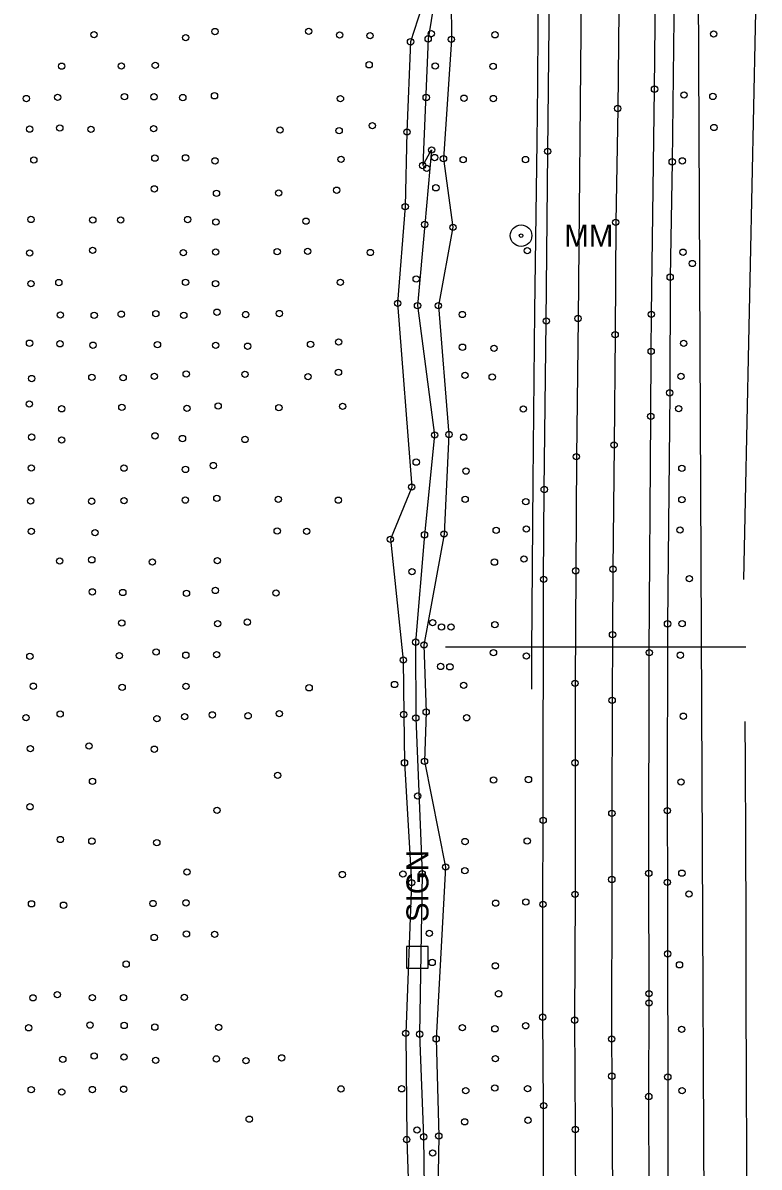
# Model space of a CAD drawing. Extents: x 20503438 to 20508873, y 7964251 to 7984667.
# Drawn here: x 20506380.3 to 20506614, y 7965237.1 to 7965600.1 of the extents above; entities that cross this region are included whole.
import ezdxf

# ---------------------------------------------------------------- set-up
doc = ezdxf.new("R2010")
doc.units = 0
for name, color, linetype in [('PhoSignTrussOverhead', 7, 'Continuous'), ('SurBreakLine', 7, 'Continuous'), ('SurDrainageArrowDown', 7, 'Continuous'), ('SurEdgeRoadPaved', 7, 'Continuous'), ('SurEdgeShoulderPaved', 7, 'Continuous'), ('SurGuardRailCable', 7, 'Continuous'), ('SurPointsNonDTM', 7, 'Continuous'), ('SurRoadPoints', 7, 'Continuous'), ('SurSurveyPoints', 7, 'Continuous')]:
    doc.layers.add(name, color=color, linetype=linetype)

msp = doc.modelspace()

# ---------------------------------------------------------------- linework, layer by layer
at = {"layer": 'PhoSignTrussOverhead'}
msp.add_line((20506514.44, 7965402.17), (20506609.7, 7965402.17), dxfattribs=at)
at = {"layer": 'SurBreakLine'}
for points in [[(20506522.39, 7965700.71), (20506522, 7965700.32), (20506516.56, 7965699.39), (20506518.84, 7965688.49), (20506515.01, 7965666.88), (20506518.2, 7965645.46), (20506516.16, 7965620.24), (20506516.31, 7965594.85), (20506513.79, 7965556.99), (20506516.81, 7965535.24), (20506512.19, 7965510.34), (20506515.52, 7965469.48), (20506513.97, 7965437.92), (20506507.59, 7965402.71), (20506508.3, 7965381.45), (20506507.78, 7965365.83), (20506514.49, 7965332.27), (20506511.48, 7965277.77), (20506512.31, 7965246.93), (20506511.6, 7965205.59), (20506511.79, 7965203.63)], [(20506511.46, 7965619.33), (20506503.35, 7965594.08), (20506502.22, 7965565.46), (20506501.65, 7965541.77), (20506499.26, 7965511.13), (20506503.71, 7965452.81), (20506496.96, 7965436.26), (20506501.03, 7965397.95), (20506501.18, 7965380.68), (20506501.43, 7965365.34), (20506503.7, 7965327.33), (20506501.82, 7965279.54), (20506502.13, 7965245.82), (20506503.57, 7965205.44), (20506503.7, 7965203.31)], [(20506569.39, 7965603.88), (20506569.1, 7965572.92), (20506568.45, 7965536.8), (20506568.27, 7965501.17), (20506567.94, 7965466.14), (20506567.58, 7965426.78), (20506567.45, 7965405.97), (20506567.32, 7965385.16), (20506567.23, 7965349.31), (20506567.21, 7965328.34), (20506567.14, 7965277.73), (20506567.21, 7965265.93), (20506567.51, 7965206.56), (20506567.54, 7965202.77)]]:
    msp.add_lwpolyline(points, dxfattribs=at)
at = {"layer": 'SurDrainageArrowDown'}
for points in [[(20506609.14, 7965423.53), (20506609.66, 7965448.52), (20506610.19, 7965473.52), (20506610.72, 7965498.73), (20506611.24, 7965523.51), (20506611.76, 7965548.5), (20506612.29, 7965573.49), (20506612.82, 7965598.63), (20506613.33, 7965623.29), (20506613.86, 7965648.48), (20506613.96, 7965653.23)], [(20506512.75, 7965618.39), (20506508.94, 7965594.99), (20506507.21, 7965554.81), (20506510.03, 7965559.76), (20506507.85, 7965536.13), (20506505.57, 7965510.38), (20506511, 7965469.31), (20506507.78, 7965437.68), (20506504.95, 7965403.63), (20506505.01, 7965379.53), (20506507.03, 7965330.13), (20506506.23, 7965279.25), (20506507.51, 7965246.68), (20506507.98, 7965205.94), (20506507.99, 7965183.58), (20506506.45, 7965157.25), (20506507.19, 7965112.35), (20506505.61, 7965065.42), (20506505.71, 7965016.95)], [(20506610.82, 7965065.24), (20506610.71, 7965090.24), (20506610.61, 7965115.23), (20506610.51, 7965140.23), (20506610.41, 7965165.23), (20506610.31, 7965190.23), (20506610.21, 7965215.23), (20506610.1, 7965240.23), (20506610, 7965265.23), (20506609.9, 7965290.23), (20506609.8, 7965315.23), (20506609.7, 7965340.23), (20506609.6, 7965365.23), (20506609.54, 7965378.43)]]:
    msp.add_lwpolyline(points, dxfattribs=at)
at = {"layer": 'SurEdgeRoadPaved'}
for points in [[(20506562.98, 7966069.12), (20506561.69, 7965956.65), (20506561.36, 7965927.21), (20506561.02, 7965904.12), (20506560.12, 7965843.51), (20506559.8, 7965821.05), (20506559.37, 7965785.5), (20506558.21, 7965668.14), (20506558.03, 7965647.17), (20506557.54, 7965608.72), (20506556.5, 7965506.31), (20506555.98, 7965462.45), (20506555.76, 7965426.25), (20506555.55, 7965390.53), (20506555.55, 7965365.32), (20506555.55, 7965323.6), (20506555.42, 7965283.68), (20506555.63, 7965249), (20506555.73, 7965220.22), (20506555.85, 7965201.63)], [(20506579.33, 7965201.74), (20506579.06, 7965228.35), (20506578.95, 7965259.46), (20506579.02, 7965289.12), (20506579.03, 7965292.09), (20506578.95, 7965330.25), (20506579.12, 7965400.3), (20506579.58, 7965475.25), (20506579.7, 7965495.86), (20506579.77, 7965507.64), (20506580.77, 7965579.04), (20506582.18, 7965713.39), (20506584.15, 7965857.73), (20506584.51, 7965883.12), (20506584.95, 7965922.01), (20506585.27, 7965953.21), (20506585.61, 7965985.81), (20506586.02, 7966017.66)]]:
    msp.add_lwpolyline(points, dxfattribs=at)
at = {"layer": 'SurEdgeShoulderPaved'}
for points in [[(20506545.59, 7965201.59), (20506545.55, 7965219.53), (20506545.56, 7965256.58), (20506545.28, 7965284.63), (20506545.36, 7965320.45), (20506545.43, 7965347.11), (20506545.59, 7965423.56), (20506545.77, 7965452.03), (20506546.43, 7965505.49), (20506546.86, 7965559.32), (20506548.13, 7965680.05), (20506548.89, 7965738.14), (20506549.41, 7965796.65), (20506550.26, 7965848.19), (20506551.65, 7965956.18), (20506552.19, 7965996.51), (20506552.57, 7966028.45), (20506552.68, 7966057.72)], [(20506592.19, 7966059.31), (20506591.79, 7966030.9), (20506591.18, 7965975.25), (20506590.93, 7965954.62), (20506589.59, 7965843.55), (20506588.16, 7965735.35), (20506587.68, 7965699.72), (20506587.42, 7965658.24), (20506587.16, 7965625.38), (20506586.88, 7965601.51), (20506586.38, 7965556.01), (20506585.73, 7965519.42), (20506585.6, 7965482.7), (20506584.9, 7965409.44), (20506584.81, 7965350.17), (20506584.84, 7965327.41), (20506584.92, 7965304.74), (20506584.98, 7965265.69), (20506584.99, 7965225.89), (20506585.23, 7965201.77)]]:
    msp.add_lwpolyline(points, dxfattribs=at)
at = {"layer": 'SurGuardRailCable'}
for points in [[(20506613.34, 7964252.79), (20506601.5, 7964822.04), (20506598.64, 7964984.08), (20506597.55, 7965074.02), (20506596.61, 7965201.81), (20506594.34, 7965701.8), (20506594.71, 7965733.27), (20506595.45, 7965806.52), (20506596.03, 7965869.84), (20506597.23, 7965978.92), (20506600.18, 7966186.78), (20506601.51, 7966279.91), (20506601.63, 7966286.68)], [(20506544.5, 7965688.68), (20506544.37, 7965670.68), (20506544.23, 7965652.66), (20506544.02, 7965624.87), (20506543.77, 7965598.66), (20506543.59, 7965580.66), (20506543.41, 7965562.43), (20506542.7, 7965508.66), (20506542.13, 7965454.69), (20506541.73, 7965400.68), (20506541.77, 7965388.69)]]:
    msp.add_lwpolyline(points, dxfattribs=at)
at = {"layer": 'SurPointsNonDTM'}
for centre in [(20506508.31, 7965576.41), (20506508.47, 7965553.92), (20506592.77, 7965523.74), (20506505.14, 7965518.82), (20506505.14, 7965460.72), (20506503.78, 7965425.97), (20506591.83, 7965423.75), (20506498.27, 7965390.18), (20506505.61, 7965354.83), (20506591.69, 7965323.75), (20506509.29, 7965311.22), (20506505.4, 7965248.86)]:
    msp.add_circle(centre, 1, dxfattribs=at)
at = {"layer": 'SurRoadPoints'}
msp.add_lwpolyline([(20506508.96, 7965303.6), (20506508.96, 7965303.6), (20506508.96, 7965307.03), (20506502.1, 7965307.03), (20506502.1, 7965300.17), (20506508.96, 7965300.17), (20506508.96, 7965303.6)], dxfattribs=at)
for radius in [3.43, 0.571]:
    msp.add_circle((20506538.42, 7965532.57), radius, dxfattribs=at)
at = {"layer": 'SurSurveyPoints'}
for centre in [(20506402.92, 7965596.33), (20506431.99, 7965595.39), (20506441.28, 7965597.32), (20506471.04, 7965597.4), (20506480.83, 7965596.23), (20506490.49, 7965596.02), (20506508.94, 7965594.99), (20506509.95, 7965596.65), (20506516.31, 7965594.85), (20506530.15, 7965596.29), (20506599.52, 7965596.57), (20506503.35, 7965594.08), (20506392.61, 7965586.34), (20506411.6, 7965586.37), (20506422.33, 7965586.63), (20506490.22, 7965586.78), (20506511.17, 7965586.37), (20506529.55, 7965586.26), (20506391.34, 7965576.47), (20506412.56, 7965576.65), (20506421.96, 7965576.62), (20506441.14, 7965576.94), (20506580.77, 7965579.04), (20506590.14, 7965577.19), (20506599.29, 7965576.74), (20506381.43, 7965576.07), (20506431.07, 7965576.38), (20506481.1, 7965576.05), (20506520.34, 7965576.18), (20506529.59, 7965576.07), (20506569.1, 7965572.92), (20506382.47, 7965566.37), (20506392.04, 7965566.75), (20506401.94, 7965566.32), (20506421.82, 7965566.51), (20506461.94, 7965566.1), (20506480.69, 7965565.9), (20506491.24, 7965567.49), (20506599.61, 7965566.88), (20506502.22, 7965565.46), (20506510.03, 7965559.76), (20506546.86, 7965559.32), (20506383.81, 7965556.6), (20506422.22, 7965557.16), (20506431.94, 7965557.25), (20506441.3, 7965556.29), (20506481.3, 7965556.76), (20506507.21, 7965554.81), (20506511, 7965557.35), (20506513.79, 7965556.99), (20506520.05, 7965556.65), (20506539.83, 7965556.71), (20506586.38, 7965556.01), (20506589.58, 7965556.29), (20506422.06, 7965547.42), (20506511.38, 7965547.76), (20506441.77, 7965545.98), (20506461.5, 7965546.13), (20506479.91, 7965546.99), (20506501.65, 7965541.77), (20506382.89, 7965537.71), (20506402.52, 7965537.53), (20506411.37, 7965537.53), (20506432.65, 7965537.68), (20506441.57, 7965536.91), (20506470.16, 7965537.17), (20506568.45, 7965536.8), (20506507.85, 7965536.13), (20506516.81, 7965535.24), (20506382.5, 7965527.04), (20506402.47, 7965527.94), (20506431.23, 7965527.18), (20506441.51, 7965527.4), (20506461.04, 7965527.47), (20506470.72, 7965527.6), (20506490.58, 7965527.23), (20506540.39, 7965527.8), (20506589.82, 7965527.32), (20506585.73, 7965519.42), (20506382.89, 7965517.37), (20506391.74, 7965517.69), (20506431.95, 7965517.75), (20506441.46, 7965517.34), (20506481.09, 7965517.75), (20506499.26, 7965511.13), (20506411.54, 7965507.67), (20506422.52, 7965507.84), (20506441.92, 7965508.29), (20506451.03, 7965507.54), (20506461.74, 7965507.86), (20506505.57, 7965510.38), (20506512.19, 7965510.34), (20506519.76, 7965507.56), (20506579.77, 7965507.64), (20506392.23, 7965507.39), (20506402.97, 7965507.27), (20506431.4, 7965507.3), (20506546.43, 7965505.49), (20506556.5, 7965506.31), (20506568.27, 7965501.17), (20506382.44, 7965498.45), (20506392.1, 7965498.27), (20506402.58, 7965497.82), (20506423.04, 7965497.98), (20506441.51, 7965497.79), (20506451.66, 7965497.5), (20506471.61, 7965498.09), (20506480.52, 7965498.84), (20506519.82, 7965497.18), (20506529.84, 7965496.81), (20506590.03, 7965498.4), (20506579.7, 7965495.86), (20506383.13, 7965487.25), (20506402.22, 7965487.63), (20506412.14, 7965487.53), (20506422.07, 7965487.96), (20506432.16, 7965488.68), (20506450.79, 7965488.55), (20506470.82, 7965487.82), (20506480.48, 7965489.24), (20506520.63, 7965488.28), (20506529.26, 7965487.74), (20506589.14, 7965487.95), (20506585.6, 7965482.7), (20506382.36, 7965479.14), (20506442.3, 7965478.54), (20506392.62, 7965477.64), (20506411.74, 7965478.14), (20506432.39, 7965477.81), (20506461.57, 7965478.01), (20506481.8, 7965478.41), (20506539.12, 7965477.57), (20506579.58, 7965475.25), (20506588.44, 7965477.7), (20506383.11, 7965468.66), (20506392.63, 7965467.72), (20506422.28, 7965469.05), (20506430.97, 7965468.21), (20506450.83, 7965467.92), (20506511, 7965469.31), (20506515.52, 7965469.48), (20506520.19, 7965468.65), (20506567.94, 7965466.14), (20506555.98, 7965462.45), (20506383.01, 7965458.87), (20506412.4, 7965458.83), (20506431.92, 7965458.41), (20506440.78, 7965459.64), (20506520.93, 7965457.88), (20506589.43, 7965458.73), (20506503.71, 7965452.81), (20506545.77, 7965452.03), (20506382.78, 7965448.42), (20506402.15, 7965448.32), (20506412.43, 7965448.49), (20506431.88, 7965448.68), (20506441.88, 7965449.23), (20506461.38, 7965448.92), (20506480.44, 7965448.66), (20506520.68, 7965448.95), (20506539.92, 7965448.2), (20506589.44, 7965448.84), (20506383.01, 7965438.77), (20506461.04, 7965438.89), (20506470.4, 7965438.78), (20506530.52, 7965439.09), (20506540.06, 7965439.51), (20506588.88, 7965439.2), (20506403.24, 7965438.34), (20506496.96, 7965436.26), (20506507.78, 7965437.68), (20506513.97, 7965437.92), (20506392.03, 7965429.37), (20506402.2, 7965429.75), (20506421.43, 7965429.05), (20506442.05, 7965429.46), (20506529.97, 7965429), (20506539.32, 7965430.02), (20506555.76, 7965426.25), (20506567.58, 7965426.78), (20506545.59, 7965423.56), (20506402.34, 7965419.57), (20506412.03, 7965419.37), (20506432.25, 7965419.08), (20506441.42, 7965420.01), (20506460.68, 7965419.23), (20506411.72, 7965409.69), (20506442.15, 7965409.47), (20506451.53, 7965409.97), (20506510.36, 7965409.82), (20506589.53, 7965409.5), (20506513.17, 7965408.45), (20506516.2, 7965408.44), (20506530.11, 7965409.18), (20506567.45, 7965405.97), (20506584.9, 7965409.44), (20506504.95, 7965403.63), (20506507.59, 7965402.71), (20506382.55, 7965399.13), (20506410.93, 7965399.33), (20506422.61, 7965400.47), (20506432.04, 7965399.47), (20506441.82, 7965399.64), (20506529.66, 7965400.27), (20506540.11, 7965399.24), (20506579.12, 7965400.3), (20506588.97, 7965399.47), (20506501.03, 7965397.95), (20506512.89, 7965395.9), (20506515.83, 7965395.79), (20506383.64, 7965389.64), (20506411.83, 7965389.29), (20506432.09, 7965389.6), (20506471.16, 7965389.14), (20506520.23, 7965389.94), (20506555.55, 7965390.53), (20506567.32, 7965385.16), (20506392.16, 7965380.83), (20506440.47, 7965380.55), (20506461.69, 7965380.93), (20506501.18, 7965380.68), (20506508.3, 7965381.45), (20506381.33, 7965379.67), (20506422.86, 7965379.33), (20506431.66, 7965379.96), (20506451.8, 7965380.26), (20506505.01, 7965379.53), (20506521.16, 7965379.63), (20506589.89, 7965380.12), (20506382.71, 7965369.8), (20506401.33, 7965370.69), (20506422.02, 7965369.65), (20506501.43, 7965365.34), (20506507.78, 7965365.83), (20506555.55, 7965365.32), (20506402.42, 7965359.48), (20506461.21, 7965361.35), (20506529.68, 7965359.89), (20506540.77, 7965360.03), (20506589.17, 7965359.24), (20506382.59, 7965351.38), (20506441.95, 7965350.25), (20506567.23, 7965349.31), (20506584.81, 7965350.17), (20506545.43, 7965347.11), (20506392.24, 7965341.01), (20506402.22, 7965340.49), (20506540.37, 7965340.55), (20506422.83, 7965340), (20506520.66, 7965340.37), (20506432.41, 7965330.71), (20506481.68, 7965329.89), (20506500.92, 7965330.07), (20506507.03, 7965330.13), (20506514.49, 7965332.27), (20506520.59, 7965331.14), (20506578.95, 7965330.25), (20506589.45, 7965330.33), (20506503.7, 7965327.33), (20506567.21, 7965328.34), (20506584.84, 7965327.41), (20506555.55, 7965323.6), (20506383.07, 7965320.6), (20506393.23, 7965320.17), (20506421.65, 7965320.71), (20506432.12, 7965320.91), (20506530.34, 7965320.81), (20506539.93, 7965321.21), (20506545.36, 7965320.45), (20506422, 7965309.94), (20506432.24, 7965311.02), (20506441.18, 7965310.91), (20506584.92, 7965304.74), (20506413.11, 7965301.48), (20506510.21, 7965302), (20506530.26, 7965300.93), (20506588.69, 7965301.25), (20506383.56, 7965290.78), (20506391.25, 7965291.81), (20506402.4, 7965290.81), (20506412.26, 7965290.83), (20506431.55, 7965290.91), (20506531.28, 7965292.06), (20506579.03, 7965292.09), (20506579.02, 7965289.12), (20506545.28, 7965284.63), (20506555.42, 7965283.68), (20506382.15, 7965281.28), (20506401.64, 7965282.13), (20506412.47, 7965282.02), (20506422.2, 7965281.49), (20506442.45, 7965281.45), (20506501.82, 7965279.54), (20506506.23, 7965279.25), (20506519.79, 7965281.31), (20506530.11, 7965280.96), (20506539.89, 7965281.92), (20506589.37, 7965280.78), (20506511.48, 7965277.77), (20506567.14, 7965277.73), (20506402.95, 7965272.35), (20506412.41, 7965272.04), (20506462.45, 7965271.74), (20506393, 7965271.3), (20506422.48, 7965270.93), (20506441.72, 7965271.41), (20506451.11, 7965270.85), (20506530.26, 7965271.5), (20506567.21, 7965265.93), (20506584.98, 7965265.69), (20506382.98, 7965261.65), (20506392.67, 7965260.89), (20506402.4, 7965261.69), (20506412.3, 7965261.8), (20506481.27, 7965261.89), (20506500.53, 7965261.93), (20506520.87, 7965261.33), (20506530.08, 7965262.19), (20506540.48, 7965261.95), (20506589.52, 7965261.33), (20506578.95, 7965259.46), (20506545.56, 7965256.58), (20506452.16, 7965252.29), (20506520.54, 7965251.44), (20506540.6, 7965251.95), (20506507.51, 7965246.68), (20506512.31, 7965246.93), (20506555.63, 7965249), (20506502.13, 7965245.82), (20506510.36, 7965241.54)]:
    msp.add_circle(centre, 1, dxfattribs=at)

# ---------------------------------------------------------------- texts
at = {"layer": 'SurRoadPoints'}
for s, rotation, p in [('MM', 360, (20506552.13, 7965529.08)), ('SIGN', 90, (20506509.03, 7965314.81))]:
    msp.add_text(s, height=6.995, rotation=rotation, dxfattribs=at).set_placement(p)

doc.saveas('drawing.dxf')
